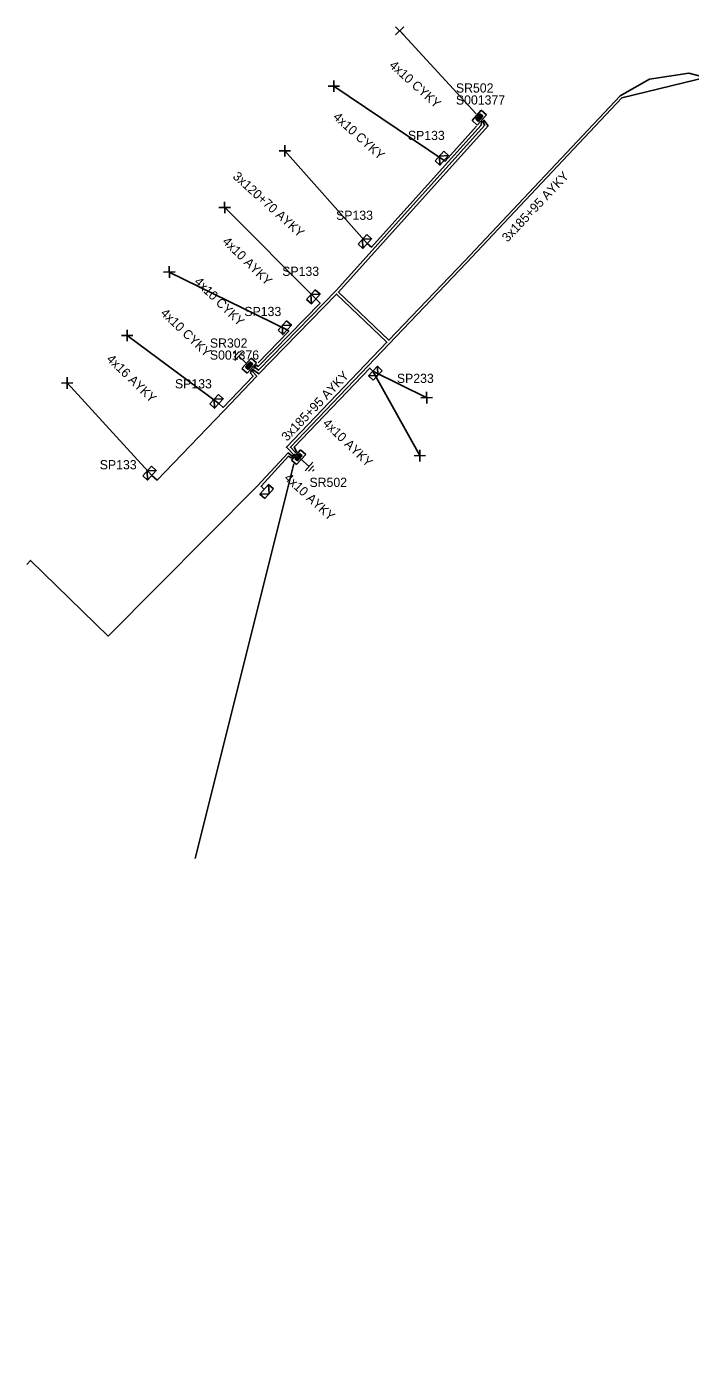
# Model space of a CAD drawing. Extents: x -762284 to -761419, y -1155250 to -1154991.
# Drawn here: x -761884.2 to -761812.4, y -1155246.2 to -1155101.8 of the extents above; entities that cross this region are included whole.
import ezdxf

# ---------------------------------------------------------------- set-up
doc = ezdxf.new("R2010")
doc.units = 0
for name, color, linetype in [('Vrstva 15', 7, 'Continuous'), ('Vrstva 28', 7, 'Continuous'), ('Vrstva 29', 7, 'Continuous'), ('Vrstva 30', 7, 'Continuous'), ('Vrstva 31', 7, 'Continuous'), ('Vrstva 33', 7, 'Continuous'), ('Vrstva 34', 7, 'Continuous'), ('Vrstva 5', 7, 'Continuous'), ('Vrstva 59', 7, 'Continuous'), ('Vrstva 6', 7, 'Continuous')]:
    doc.layers.add(name, color=color, linetype=linetype)

msp = doc.modelspace()

# ---------------------------------------------------------------- linework, layer by layer
at = {"layer": 'Vrstva 15'}
for points in [[(-761861.791, -1155137.179), (-761861.702, -1155137.081)], [(-761861.724, -1155137.577), (-761861.197, -1155136.991)], [(-761861.702, -1155137.081), (-761861.616, -1155136.986)], [(-761861.655, -1155137.963), (-761860.819, -1155137.034)], [(-761860.308, -1155138.335), (-761861.237, -1155137.499)], [(-761854.561, -1155148.595), (-761853.632, -1155149.431)], [(-761853.214, -1155148.967), (-761854.05, -1155149.896)], [(-761853.145, -1155149.353), (-761853.672, -1155149.939)], [(-761853.168, -1155149.85), (-761853.253, -1155149.945)], [(-761853.079, -1155149.751), (-761853.168, -1155149.85)]]:
    msp.add_lwpolyline(points, dxfattribs=at)
at = {"layer": 'Vrstva 28'}
for points in [[(-761834.985, -1155110.855), (-761835.988, -1155111.969)], [(-761835.093, -1155111.258), (-761835.591, -1155111.811)], [(-761835.09, -1155111.324), (-761835.524, -1155111.807)], [(-761835.086, -1155111.391), (-761835.458, -1155111.804)], [(-761835.431, -1155112.471), (-761834.427, -1155111.356)], [(-761834.812, -1155111.51), (-761835.093, -1155111.258)], [(-761834.879, -1155111.514), (-761835.09, -1155111.324)], [(-761834.946, -1155111.517), (-761835.086, -1155111.391)], [(-761834.427, -1155111.356), (-761834.985, -1155110.855)], [(-761835.988, -1155111.969), (-761835.431, -1155112.471)], [(-761835.591, -1155111.811), (-761835.31, -1155112.063)], [(-761835.524, -1155111.807), (-761835.314, -1155111.997)], [(-761835.458, -1155111.804), (-761835.317, -1155111.93)], [(-761835.083, -1155111.458), (-761835.391, -1155111.8)], [(-761835.391, -1155111.8), (-761835.321, -1155111.863)], [(-761835.075, -1155111.52), (-761835.328, -1155111.801)], [(-761835.321, -1155111.863), (-761835.012, -1155111.521)], [(-761835.317, -1155111.93), (-761834.946, -1155111.517)], [(-761835.314, -1155111.997), (-761834.879, -1155111.514)], [(-761835.31, -1155112.063), (-761834.812, -1155111.51)], [(-761835.012, -1155111.521), (-761835.083, -1155111.458)], [(-761859.884, -1155137.704), (-761860.888, -1155138.819)], [(-761860.888, -1155138.819), (-761860.33, -1155139.321)], [(-761859.993, -1155138.107), (-761860.491, -1155138.66)], [(-761860.491, -1155138.66), (-761860.21, -1155138.913)], [(-761859.989, -1155138.174), (-761860.424, -1155138.657)], [(-761860.424, -1155138.657), (-761860.213, -1155138.847)], [(-761859.986, -1155138.241), (-761860.357, -1155138.653)], [(-761860.357, -1155138.653), (-761860.217, -1155138.78)], [(-761860.33, -1155139.321), (-761859.327, -1155138.206)], [(-761859.982, -1155138.308), (-761860.29, -1155138.65)], [(-761860.29, -1155138.65), (-761860.22, -1155138.713)], [(-761859.975, -1155138.37), (-761860.228, -1155138.651)], [(-761860.22, -1155138.713), (-761859.912, -1155138.371)], [(-761860.217, -1155138.78), (-761859.845, -1155138.367)], [(-761860.213, -1155138.847), (-761859.779, -1155138.364)], [(-761860.21, -1155138.913), (-761859.712, -1155138.36)], [(-761859.712, -1155138.36), (-761859.993, -1155138.107)], [(-761859.779, -1155138.364), (-761859.989, -1155138.174)], [(-761859.845, -1155138.367), (-761859.986, -1155138.241)], [(-761859.912, -1155138.371), (-761859.982, -1155138.308)], [(-761859.327, -1155138.206), (-761859.884, -1155137.704)], [(-761854.539, -1155147.609), (-761855.543, -1155148.724)], [(-761855.543, -1155148.724), (-761854.986, -1155149.225)], [(-761854.66, -1155148.017), (-761855.158, -1155148.57)], [(-761855.158, -1155148.57), (-761854.877, -1155148.823)], [(-761854.656, -1155148.083), (-761855.091, -1155148.566)], [(-761855.091, -1155148.566), (-761854.88, -1155148.756)], [(-761854.653, -1155148.15), (-761855.024, -1155148.563)], [(-761855.024, -1155148.563), (-761854.884, -1155148.689)], [(-761854.986, -1155149.225), (-761853.982, -1155148.111)], [(-761854.649, -1155148.217), (-761854.958, -1155148.559)], [(-761854.958, -1155148.559), (-761854.887, -1155148.622)], [(-761854.895, -1155148.56), (-761854.642, -1155148.279)], [(-761854.887, -1155148.622), (-761854.579, -1155148.28)], [(-761854.884, -1155148.689), (-761854.512, -1155148.277)], [(-761854.88, -1155148.756), (-761854.446, -1155148.273)], [(-761854.877, -1155148.823), (-761854.379, -1155148.27)], [(-761854.379, -1155148.27), (-761854.66, -1155148.017)], [(-761854.446, -1155148.273), (-761854.656, -1155148.083)], [(-761854.512, -1155148.277), (-761854.653, -1155148.15)], [(-761854.579, -1155148.28), (-761854.649, -1155148.217)], [(-761853.982, -1155148.111), (-761854.539, -1155147.609)]]:
    msp.add_lwpolyline(points, dxfattribs=at)
at = {"layer": 'Vrstva 31'}
for points in [[(-761839.05, -1155115.299), (-761839.986, -1155116.34)], [(-761839.05, -1155115.299), (-761838.529, -1155115.768), (-761839.466, -1155116.808), (-761839.986, -1155116.34)], [(-761839.518, -1155115.819), (-761838.529, -1155115.768)], [(-761839.518, -1155115.819), (-761839.466, -1155116.808)], [(-761847.38, -1155124.299), (-761848.317, -1155125.339)], [(-761847.38, -1155124.299), (-761846.86, -1155124.767), (-761847.797, -1155125.808), (-761848.317, -1155125.339)], [(-761847.849, -1155124.819), (-761846.86, -1155124.767)], [(-761847.849, -1155124.819), (-761847.797, -1155125.808)], [(-761852.951, -1155130.299), (-761853.887, -1155131.339)], [(-761852.951, -1155130.299), (-761852.43, -1155130.767), (-761853.367, -1155131.807), (-761853.887, -1155131.339)], [(-761853.419, -1155130.819), (-761852.43, -1155130.767)], [(-761853.419, -1155130.819), (-761853.367, -1155131.807)], [(-761856.05, -1155133.639), (-761856.987, -1155134.68)], [(-761856.05, -1155133.639), (-761855.53, -1155134.108), (-761856.467, -1155135.148), (-761856.987, -1155134.68)], [(-761856.519, -1155134.159), (-761855.53, -1155134.108)], [(-761856.519, -1155134.159), (-761856.467, -1155135.148)], [(-761846.677, -1155140.081), (-761847.189, -1155139.604), (-761846.234, -1155138.58), (-761845.722, -1155139.058)], [(-761846.199, -1155139.569), (-761846.234, -1155138.58)], [(-761846.199, -1155139.569), (-761847.189, -1155139.604)], [(-761846.677, -1155140.081), (-761845.722, -1155139.058)], [(-761863.441, -1155141.619), (-761864.377, -1155142.659)], [(-761863.441, -1155141.619), (-761862.92, -1155142.087), (-761863.857, -1155143.128), (-761864.377, -1155142.659)], [(-761863.909, -1155142.139), (-761862.92, -1155142.087)], [(-761863.909, -1155142.139), (-761863.857, -1155143.128)], [(-761870.673, -1155149.398), (-761871.627, -1155150.422)], [(-761870.673, -1155149.398), (-761870.161, -1155149.875), (-761871.116, -1155150.899), (-761871.627, -1155150.422)], [(-761871.15, -1155149.91), (-761870.161, -1155149.875)], [(-761871.15, -1155149.91), (-761871.116, -1155150.899)], [(-761858.42, -1155152.901), (-761858.94, -1155152.432), (-761858.003, -1155151.392), (-761857.483, -1155151.86)], [(-761858.42, -1155152.901), (-761857.483, -1155151.86)], [(-761857.951, -1155152.38), (-761858.003, -1155151.392)], [(-761857.951, -1155152.38), (-761858.94, -1155152.432)]]:
    msp.add_lwpolyline(points, dxfattribs=at)
at = {"layer": 'Vrstva 34'}
for points in [[(-761844.252, -1155101.808), (-761843.368, -1155102.692)], [(-761844.252, -1155102.692), (-761843.368, -1155101.808)], [(-761851.565, -1155108.261), (-761850.315, -1155108.239)], [(-761850.929, -1155108.875), (-761850.951, -1155107.625)], [(-761856.875, -1155115.261), (-761855.625, -1155115.239)], [(-761856.239, -1155115.875), (-761856.261, -1155114.625)], [(-761863.375, -1155121.391), (-761862.125, -1155121.369)], [(-761862.739, -1155122.005), (-761862.761, -1155120.755)], [(-761869.375, -1155128.391), (-761868.125, -1155128.369)], [(-761868.739, -1155129.005), (-761868.761, -1155127.755)], [(-761873.935, -1155135.261), (-761872.685, -1155135.239)], [(-761873.299, -1155135.875), (-761873.321, -1155134.625)], [(-761879.799, -1155141.005), (-761879.821, -1155139.755)], [(-761880.435, -1155140.391), (-761879.185, -1155140.369)], [(-761840.879, -1155142.605), (-761840.901, -1155141.355)], [(-761841.515, -1155141.991), (-761840.265, -1155141.969)], [(-761842.255, -1155148.261), (-761841.005, -1155148.239)], [(-761841.619, -1155148.875), (-761841.641, -1155147.625)]]:
    msp.add_lwpolyline(points, dxfattribs=at)
at = {"layer": 'Vrstva 5'}
for points in [[(-761855.05, -1155147.98), (-761855.07, -1155147.93), (-761855.65, -1155147.35), (-761836.57, -1155127.39), (-761819.77, -1155109.53), (-761810.41, -1155107.25), (-761806.23, -1155106.72), (-761803.04, -1155107.44), (-761797.02, -1155113.03), (-761797.22, -1155113.26), (-761795.25, -1155115.01), (-761795.31, -1155115.22)], [(-761676.7, -1155245.18), (-761673.46, -1155246.2), (-761670.79, -1155237.14), (-761684.52, -1155223.2), (-761704.2, -1155203.38), (-761720.29, -1155187.3), (-761737.44, -1155169.6), (-761748.74, -1155161.1), (-761800.66, -1155115.37), (-761802.76, -1155113.49), (-761809.21, -1155107.71), (-761812.53, -1155106.85), (-761816.77, -1155107.49), (-761819.95, -1155109.3), (-761836.79, -1155127.18), (-761844.99, -1155135.76), (-761850.45, -1155130.54), (-761834.24, -1155112.53), (-761834.72, -1155111.94), (-761834.75, -1155111.9)], [(-761834.84, -1155112), (-761834.75, -1155112.19), (-761834.63, -1155112.52), (-761850.67, -1155130.34), (-761859.11, -1155139), (-761859.41, -1155138.75), (-761859.65, -1155138.75)], [(-761834.92, -1155112.09), (-761835.03, -1155112.51), (-761846.88, -1155125.67), (-761847.33, -1155125.29)], [(-761835.5, -1155112.58), (-761838.91, -1155116.37), (-761839, -1155116.29)], [(-761859.73, -1155138.85), (-761859.6, -1155138.98), (-761859.08, -1155139.41), (-761850.66, -1155130.76), (-761845.2, -1155135.98), (-761856.08, -1155147.34), (-761855.26, -1155148.16), (-761855.14, -1155148.08)], [(-761859.56, -1155138.66), (-761859.3, -1155138.45), (-761859.13, -1155138.59), (-761852.44, -1155131.73), (-761852.9, -1155131.29)], [(-761859.15, -1155138.19), (-761855.83, -1155134.77), (-761856, -1155134.63)], [(-761854.96, -1155147.89), (-761855.23, -1155147.34), (-761847.03, -1155138.78), (-761846.71, -1155139.09)], [(-761859.82, -1155138.94), (-761859.72, -1155139.19), (-761859.29, -1155139.64), (-761862.9, -1155143.45), (-761870.06, -1155150.89), (-761870.64, -1155150.39)], [(-761859.91, -1155139.04), (-761859.96, -1155139.34), (-761859.69, -1155139.63), (-761862.92, -1155143.03), (-761863.39, -1155142.61)], [(-761855.22, -1155148.18), (-761855.49, -1155148.27), (-761855.89, -1155147.95), (-761859.23, -1155151.57), (-761875.38, -1155167.79), (-761883.78, -1155159.59), (-761884.19, -1155160.03)], [(-761855.31, -1155148.27), (-761855.56, -1155148.48), (-761855.84, -1155148.31), (-761858.82, -1155151.56), (-761858.47, -1155151.91)]]:
    msp.add_lwpolyline(points, dxfattribs=at)
at = {"layer": 'Vrstva 59'}
for points in [[(-761835.53, -1155111.26), (-761843.81, -1155102.25)], [(-761839, -1155116.29), (-761850.94, -1155108.25)], [(-761847.33, -1155125.29), (-761856.25, -1155115.25)], [(-761852.9, -1155131.29), (-761862.75, -1155121.38)], [(-761856, -1155134.63), (-761868.75, -1155128.38)], [(-761863.39, -1155142.61), (-761873.31, -1155135.25)], [(-761846.71, -1155139.09), (-761840.89, -1155141.98)], [(-761846.71, -1155139.09), (-761841.63, -1155148.25)], [(-761870.64, -1155150.39), (-761879.81, -1155140.38)], [(-761855.28, -1155149.14), (-761865.94, -1155191.88)]]:
    msp.add_lwpolyline(points, dxfattribs=at)

# ---------------------------------------------------------------- texts
at = {"layer": 'Vrstva 29'}
for s, p in [('S001377', (-761837.73, -1155110.24)), ('S001376', (-761864.36, -1155137.86))]:
    msp.add_text(s, height=0.9943, dxfattribs=at).set_placement(p)
at = {"layer": 'Vrstva 30'}
for s, p in [('SR502', (-761837.73, -1155108.94)), ('SR302', (-761864.36, -1155136.56)), ('SR502', (-761853.58, -1155151.64))]:
    msp.add_text(s, height=0.9943, dxfattribs=at).set_placement(p)
at = {"layer": 'Vrstva 33'}
for s, p in [('SP133', (-761842.93, -1155114.08)), ('SP133', (-761850.7, -1155122.72)), ('SP133', (-761856.53, -1155128.79)), ('SP133', (-761860.63, -1155133.14)), ('SP133', (-761868.14, -1155140.97)), ('SP233', (-761844.12, -1155140.38)), ('SP133', (-761876.28, -1155149.73))]:
    msp.add_text(s, height=0.9943, dxfattribs=at).set_placement(p)
at = {"layer": 'Vrstva 6'}
for s, height, rotation, p in [('4x10 CYKY', 0.9943, 318.03486, (-761845.02, -1155106.11)), ('4x10 CYKY', 0.9943, 317.99884, (-761851.1, -1155111.7)), ('3x120+70 AYKY', 0.99429, 318.01705, (-761861.96, -1155118.14)), ('3x185+95 AYKY', 0.99429, 46.72539, (-761832.14, -1155125.2)), ('4x10 AYKY', 0.9943, 315.74878, (-761863.08, -1155125.16)), ('4x10 CYKY', 0.9943, 315.78342, (-761866.13, -1155129.51)), ('4x10 CYKY', 0.9943, 316.58035, (-761869.78, -1155132.92)), ('4x16 AYKY', 0.9943, 316.11823, (-761875.62, -1155137.89)), ('3x185+95 AYKY', 0.99429, 46.25941, (-761856.01, -1155146.76)), ('4x10 AYKY', 0.9943, 316.24782, (-761852.23, -1155144.85)), ('4x10 AYKY', 0.9943, 317.51273, (-761856.4, -1155150.78))]:
    msp.add_text(s, height=height, rotation=rotation, dxfattribs=at).set_placement(p)

doc.saveas('drawing.dxf')
